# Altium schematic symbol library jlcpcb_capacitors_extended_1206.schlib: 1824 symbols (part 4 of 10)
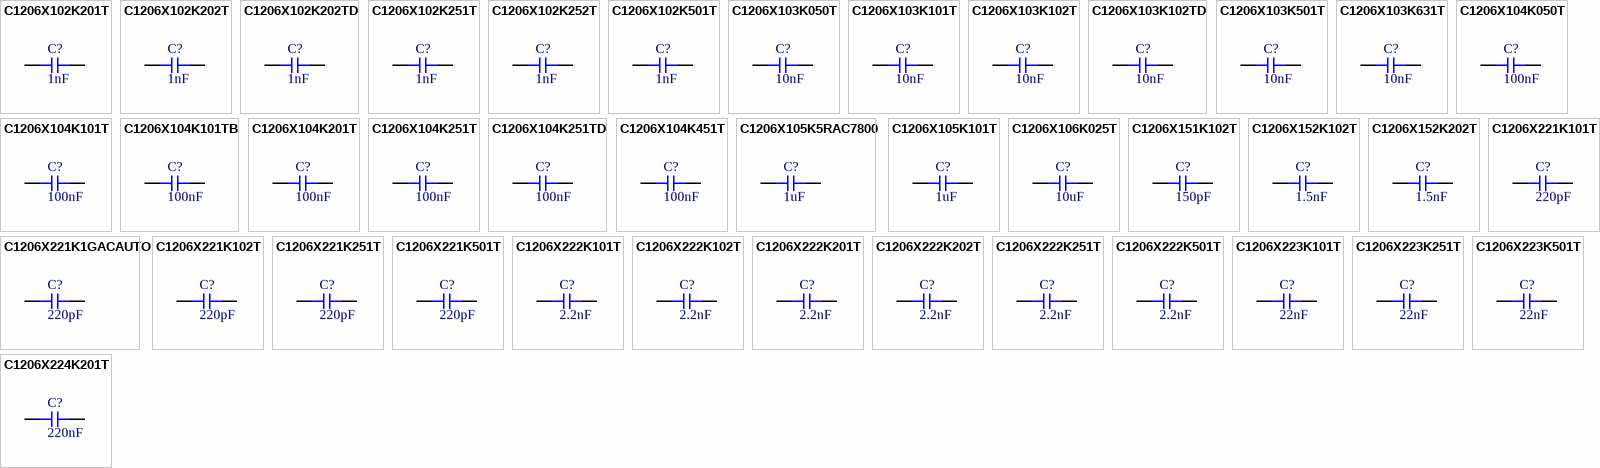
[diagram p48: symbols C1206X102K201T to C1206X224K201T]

## C1206X104K451T
designator C?  Capacitance: 100nF  (hidden comment: *)
Capacitor, Ceramic (MLCC), 100nF, ±10%, 450V, X7R, ±10%, SMD 1206; Manufacturer: IHHEC(HOLY STONE ENTERPRISE CO., LTD); Manufacturer Part Number: C1206X104K451T
footprint CAP-1206 (1206 (3216M) Capacitor)
pins: 1, 2

## C1206X105K5RAC7800
designator C?  Capacitance: 1uF  (hidden comment: *)
Capacitor, Ceramic (MLCC), 1uF, ±10%, 50V, X7R, ±10%, SMD 1206; Manufacturer: KEMET; Manufacturer Part Number: C1206X105K5RAC7800
footprint CAP-1206 (1206 (3216M) Capacitor)
pins: 1, 2

## C1206X105K101T
designator C?  Capacitance: 1uF  (hidden comment: *)
Capacitor, Ceramic (MLCC), 1uF, ±10%, 100V, X7R, ±10%, SMD 1206; Manufacturer: IHHEC(HOLY STONE ENTERPRISE CO., LTD); Manufacturer Part Number: C1206X105K101T
footprint CAP-1206 (1206 (3216M) Capacitor)
pins: 1, 2

## C1206X106K025T
designator C?  Capacitance: 10uF  (hidden comment: *)
Capacitor, Ceramic (MLCC), 10uF, ±10%, 25V, X7R, ±10%, SMD 1206; Manufacturer: IHHEC(HOLY STONE ENTERPRISE CO., LTD); Manufacturer Part Number: C1206X106K025T
footprint CAP-1206 (1206 (3216M) Capacitor)
pins: 1, 2

## C1206X151K102T
designator C?  Capacitance: 150pF  (hidden comment: *)
Capacitor, Ceramic (MLCC), 150pF, ±10%, 1kV, X7R, ±10%, SMD 1206; Manufacturer: IHHEC(HOLY STONE ENTERPRISE CO., LTD); Manufacturer Part Number: C1206X151K102T
footprint CAP-1206 (1206 (3216M) Capacitor)
pins: 1, 2

## C1206X152K102T
designator C?  Capacitance: 1.5nF  (hidden comment: *)
Capacitor, Ceramic (MLCC), 1.5nF, ±10%, 1kV, X7R, ±10%, SMD 1206; Manufacturer: IHHEC(HOLY STONE ENTERPRISE CO., LTD); Manufacturer Part Number: C1206X152K102T
footprint CAP-1206 (1206 (3216M) Capacitor)
pins: 1, 2

## C1206X152K202T
designator C?  Capacitance: 1.5nF  (hidden comment: *)
Capacitor, Ceramic (MLCC), 1.5nF, ±10%, 2kV, X7R, ±10%, SMD 1206; Manufacturer: IHHEC(HOLY STONE ENTERPRISE CO., LTD); Manufacturer Part Number: C1206X152K202T
footprint CAP-1206 (1206 (3216M) Capacitor)
pins: 1, 2

## C1206X221K1GACAUTO
designator C?  Capacitance: 220pF  (hidden comment: *)
Capacitor, Ceramic (MLCC), 220pF, ±10%, 100V, C0G, ±10%, SMD 1206; Manufacturer: KEMET; Manufacturer Part Number: C1206X221K1GACAUTO
footprint CAP-1206 (1206 (3216M) Capacitor)
pins: 1, 2

## C1206X221K101T
designator C?  Capacitance: 220pF  (hidden comment: *)
Capacitor, Ceramic (MLCC), 220pF, ±10%, 100V, X7R, ±10%, SMD 1206; Manufacturer: IHHEC(HOLY STONE ENTERPRISE CO., LTD); Manufacturer Part Number: C1206X221K101T
footprint CAP-1206 (1206 (3216M) Capacitor)
pins: 1, 2

## C1206X221K102T
designator C?  Capacitance: 220pF  (hidden comment: *)
Capacitor, Ceramic (MLCC), 220pF, ±10%, 1kV, X7R, ±10%, SMD 1206; Manufacturer: IHHEC(HOLY STONE ENTERPRISE CO., LTD); Manufacturer Part Number: C1206X221K102T
footprint CAP-1206 (1206 (3216M) Capacitor)
pins: 1, 2

## C1206X221K251T
designator C?  Capacitance: 220pF  (hidden comment: *)
Capacitor, Ceramic (MLCC), 220pF, ±10%, 250V, X7R, ±10%, SMD 1206; Manufacturer: IHHEC(HOLY STONE ENTERPRISE CO., LTD); Manufacturer Part Number: C1206X221K251T
footprint CAP-1206 (1206 (3216M) Capacitor)
pins: 1, 2

## C1206X221K501T
designator C?  Capacitance: 220pF  (hidden comment: *)
Capacitor, Ceramic (MLCC), 220pF, ±10%, 500V, X7R, ±10%, SMD 1206; Manufacturer: IHHEC(HOLY STONE ENTERPRISE CO., LTD); Manufacturer Part Number: C1206X221K501T
footprint CAP-1206 (1206 (3216M) Capacitor)
pins: 1, 2

## C1206X222K101T
designator C?  Capacitance: 2.2nF  (hidden comment: *)
Capacitor, Ceramic (MLCC), 2.2nF, ±10%, 100V, X7R, ±10%, SMD 1206; Manufacturer: IHHEC(HOLY STONE ENTERPRISE CO., LTD); Manufacturer Part Number: C1206X222K101T
footprint CAP-1206 (1206 (3216M) Capacitor)
pins: 1, 2

## C1206X222K102T
designator C?  Capacitance: 2.2nF  (hidden comment: *)
Capacitor, Ceramic (MLCC), 2.2nF, ±10%, 1kV, X7R, ±10%, SMD 1206; Manufacturer: IHHEC(HOLY STONE ENTERPRISE CO., LTD); Manufacturer Part Number: C1206X222K102T
footprint CAP-1206 (1206 (3216M) Capacitor)
pins: 1, 2

## C1206X222K201T
designator C?  Capacitance: 2.2nF  (hidden comment: *)
Capacitor, Ceramic (MLCC), 2.2nF, ±10%, 200V, X7R, ±10%, SMD 1206; Manufacturer: IHHEC(HOLY STONE ENTERPRISE CO., LTD); Manufacturer Part Number: C1206X222K201T
footprint CAP-1206 (1206 (3216M) Capacitor)
pins: 1, 2

## C1206X222K202T
designator C?  Capacitance: 2.2nF  (hidden comment: *)
Capacitor, Ceramic (MLCC), 2.2nF, ±10%, 2kV, X7R, ±10%, SMD 1206; Manufacturer: IHHEC(HOLY STONE ENTERPRISE CO., LTD); Manufacturer Part Number: C1206X222K202T
footprint CAP-1206 (1206 (3216M) Capacitor)
pins: 1, 2

## C1206X222K251T
designator C?  Capacitance: 2.2nF  (hidden comment: *)
Capacitor, Ceramic (MLCC), 2.2nF, ±10%, 250V, X7R, ±10%, SMD 1206; Manufacturer: IHHEC(HOLY STONE ENTERPRISE CO., LTD); Manufacturer Part Number: C1206X222K251T
footprint CAP-1206 (1206 (3216M) Capacitor)
pins: 1, 2

## C1206X222K501T
designator C?  Capacitance: 2.2nF  (hidden comment: *)
Capacitor, Ceramic (MLCC), 2.2nF, ±10%, 500V, X7R, ±10%, SMD 1206; Manufacturer: IHHEC(HOLY STONE ENTERPRISE CO., LTD); Manufacturer Part Number: C1206X222K501T
footprint CAP-1206 (1206 (3216M) Capacitor)
pins: 1, 2

## C1206X223K101T
designator C?  Capacitance: 22nF  (hidden comment: *)
Capacitor, Ceramic (MLCC), 22nF, ±10%, 100V, X7R, ±10%, SMD 1206; Manufacturer: IHHEC(HOLY STONE ENTERPRISE CO., LTD); Manufacturer Part Number: C1206X223K101T
footprint CAP-1206 (1206 (3216M) Capacitor)
pins: 1, 2

## C1206X223K251T
designator C?  Capacitance: 22nF  (hidden comment: *)
Capacitor, Ceramic (MLCC), 22nF, ±10%, 250V, X7R, ±10%, SMD 1206; Manufacturer: IHHEC(HOLY STONE ENTERPRISE CO., LTD); Manufacturer Part Number: C1206X223K251T
footprint CAP-1206 (1206 (3216M) Capacitor)
pins: 1, 2

## C1206X223K501T
designator C?  Capacitance: 22nF  (hidden comment: *)
Capacitor, Ceramic (MLCC), 22nF, ±10%, 500V, X7R, ±10%, SMD 1206; Manufacturer: IHHEC(HOLY STONE ENTERPRISE CO., LTD); Manufacturer Part Number: C1206X223K501T
footprint CAP-1206 (1206 (3216M) Capacitor)
pins: 1, 2

## C1206X224K201T
designator C?  Capacitance: 220nF  (hidden comment: *)
Capacitor, Ceramic (MLCC), 220nF, ±10%, 200V, X7R, ±10%, SMD 1206; Manufacturer: IHHEC(HOLY STONE ENTERPRISE CO., LTD); Manufacturer Part Number: C1206X224K201T
footprint CAP-1206 (1206 (3216M) Capacitor)
pins: 1, 2

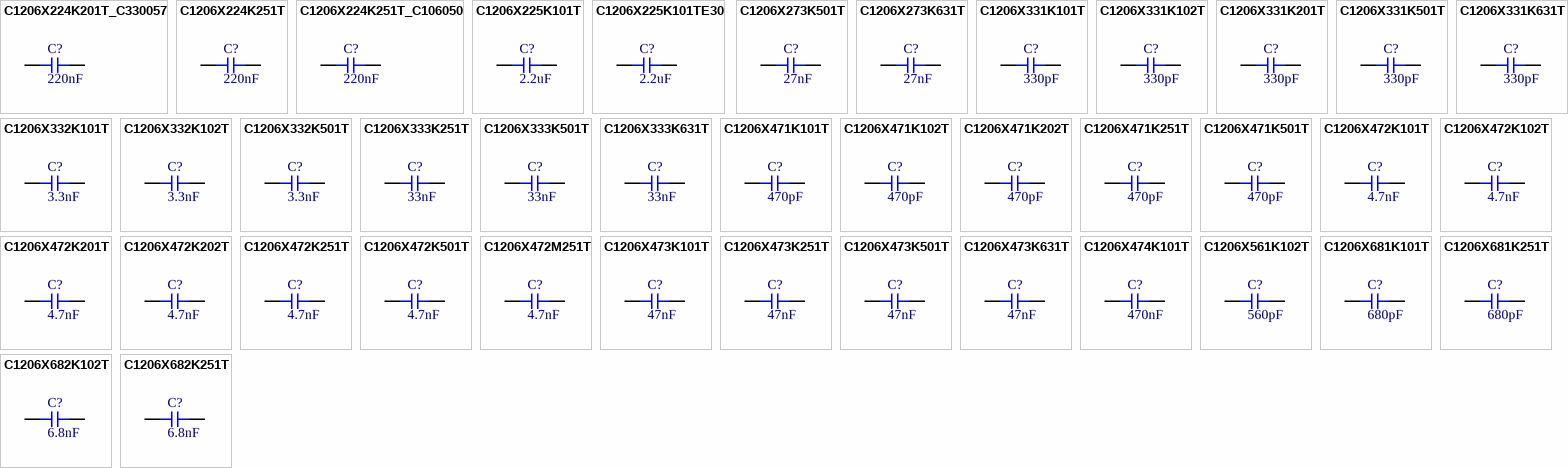
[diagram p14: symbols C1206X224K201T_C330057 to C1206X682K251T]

## C1206X224K201T_C330057
designator C?  Capacitance: 220nF  (hidden comment: *)
Capacitor, Ceramic (MLCC), 220nF, ±10%, 200V, X7R, ±10%, SMD 1206; Manufacturer: IHHEC(HOLY STONE ENTERPRISE CO., LTD); Manufacturer Part Number: C1206X224K201T
footprint CAP-1206 (1206 (3216M) Capacitor)
pins: 1, 2

## C1206X224K251T
designator C?  Capacitance: 220nF  (hidden comment: *)
Capacitor, Ceramic (MLCC), 220nF, ±10%, 250V, X7R, ±10%, SMD 1206; Manufacturer: IHHEC(HOLY STONE ENTERPRISE CO., LTD); Manufacturer Part Number: C1206X224K251T
footprint CAP-1206 (1206 (3216M) Capacitor)
pins: 1, 2

## C1206X224K251T_C106050
designator C?  Capacitance: 220nF  (hidden comment: *)
Capacitor, Ceramic (MLCC), 220nF, ±10%, 250V, X7R, ±10%, SMD 1206; Manufacturer: IHHEC(HOLY STONE ENTERPRISE CO., LTD); Manufacturer Part Number: C1206X224K251T
footprint CAP-1206 (1206 (3216M) Capacitor)
pins: 1, 2

## C1206X225K101T
designator C?  Capacitance: 2.2uF  (hidden comment: *)
Capacitor, Ceramic (MLCC), 2.2uF, ±10%, 100V, X7R, ±10%, SMD 1206; Manufacturer: IHHEC(HOLY STONE ENTERPRISE CO., LTD); Manufacturer Part Number: C1206X225K101T
footprint CAP-1206 (1206 (3216M) Capacitor)
pins: 1, 2

## C1206X225K101TE30
designator C?  Capacitance: 2.2uF  (hidden comment: *)
Capacitor, Ceramic (MLCC), 2.2uF, ±10%, 100V, X7R, ±10%, SMD 1206; Manufacturer: IHHEC(HOLY STONE ENTERPRISE CO., LTD); Manufacturer Part Number: C1206X225K101TE30
footprint CAP-1206 (1206 (3216M) Capacitor)
pins: 1, 2

## C1206X273K501T
designator C?  Capacitance: 27nF  (hidden comment: *)
Capacitor, Ceramic (MLCC), 27nF, ±10%, 500V, X7R, ±10%, SMD 1206; Manufacturer: IHHEC(HOLY STONE ENTERPRISE CO., LTD); Manufacturer Part Number: C1206X273K501T
footprint CAP-1206 (1206 (3216M) Capacitor)
pins: 1, 2

## C1206X273K631T
designator C?  Capacitance: 27nF  (hidden comment: *)
Capacitor, Ceramic (MLCC), 27nF, ±10%, 630V, X7R, ±10%, SMD 1206; Manufacturer: IHHEC(HOLY STONE ENTERPRISE CO., LTD); Manufacturer Part Number: C1206X273K631T
footprint CAP-1206 (1206 (3216M) Capacitor)
pins: 1, 2

## C1206X331K101T
designator C?  Capacitance: 330pF  (hidden comment: *)
Capacitor, Ceramic (MLCC), 330pF, ±10%, 100V, X7R, ±10%, SMD 1206; Manufacturer: IHHEC(HOLY STONE ENTERPRISE CO., LTD); Manufacturer Part Number: C1206X331K101T
footprint CAP-1206 (1206 (3216M) Capacitor)
pins: 1, 2

## C1206X331K102T
designator C?  Capacitance: 330pF  (hidden comment: *)
Capacitor, Ceramic (MLCC), 330pF, ±10%, 1kV, X7R, ±10%, SMD 1206; Manufacturer: IHHEC(HOLY STONE ENTERPRISE CO., LTD); Manufacturer Part Number: C1206X331K102T
footprint CAP-1206 (1206 (3216M) Capacitor)
pins: 1, 2

## C1206X331K201T
designator C?  Capacitance: 330pF  (hidden comment: *)
Capacitor, Ceramic (MLCC), 330pF, ±10%, 200V, X7R, ±10%, SMD 1206; Manufacturer: IHHEC(HOLY STONE ENTERPRISE CO., LTD); Manufacturer Part Number: C1206X331K201T
footprint CAP-1206 (1206 (3216M) Capacitor)
pins: 1, 2

## C1206X331K501T
designator C?  Capacitance: 330pF  (hidden comment: *)
Capacitor, Ceramic (MLCC), 330pF, ±10%, 500V, X7R, ±10%, SMD 1206; Manufacturer: IHHEC(HOLY STONE ENTERPRISE CO., LTD); Manufacturer Part Number: C1206X331K501T
footprint CAP-1206 (1206 (3216M) Capacitor)
pins: 1, 2

## C1206X331K631T
designator C?  Capacitance: 330pF  (hidden comment: *)
Capacitor, Ceramic (MLCC), 330pF, ±10%, 630V, X7R, ±10%, SMD 1206; Manufacturer: IHHEC(HOLY STONE ENTERPRISE CO., LTD); Manufacturer Part Number: C1206X331K631T
footprint CAP-1206 (1206 (3216M) Capacitor)
pins: 1, 2

## C1206X332K101T
designator C?  Capacitance: 3.3nF  (hidden comment: *)
Capacitor, Ceramic (MLCC), 3.3nF, ±10%, 100V, X7R, ±10%, SMD 1206; Manufacturer: IHHEC(HOLY STONE ENTERPRISE CO., LTD); Manufacturer Part Number: C1206X332K101T
footprint CAP-1206 (1206 (3216M) Capacitor)
pins: 1, 2

## C1206X332K102T
designator C?  Capacitance: 3.3nF  (hidden comment: *)
Capacitor, Ceramic (MLCC), 3.3nF, ±10%, 1kV, X7R, ±10%, SMD 1206; Manufacturer: IHHEC(HOLY STONE ENTERPRISE CO., LTD); Manufacturer Part Number: C1206X332K102T
footprint CAP-1206 (1206 (3216M) Capacitor)
pins: 1, 2

## C1206X332K501T
designator C?  Capacitance: 3.3nF  (hidden comment: *)
Capacitor, Ceramic (MLCC), 3.3nF, ±10%, 500V, X7R, ±10%, SMD 1206; Manufacturer: IHHEC(HOLY STONE ENTERPRISE CO., LTD); Manufacturer Part Number: C1206X332K501T
footprint CAP-1206 (1206 (3216M) Capacitor)
pins: 1, 2

## C1206X333K251T
designator C?  Capacitance: 33nF  (hidden comment: *)
Capacitor, Ceramic (MLCC), 33nF, ±10%, 250V, X7R, ±10%, SMD 1206; Manufacturer: IHHEC(HOLY STONE ENTERPRISE CO., LTD); Manufacturer Part Number: C1206X333K251T
footprint CAP-1206 (1206 (3216M) Capacitor)
pins: 1, 2

## C1206X333K501T
designator C?  Capacitance: 33nF  (hidden comment: *)
Capacitor, Ceramic (MLCC), 33nF, ±10%, 500V, X7R, ±10%, SMD 1206; Manufacturer: IHHEC(HOLY STONE ENTERPRISE CO., LTD); Manufacturer Part Number: C1206X333K501T
footprint CAP-1206 (1206 (3216M) Capacitor)
pins: 1, 2

## C1206X333K631T
designator C?  Capacitance: 33nF  (hidden comment: *)
Capacitor, Ceramic (MLCC), 33nF, ±10%, 630V, X7R, ±10%, SMD 1206; Manufacturer: IHHEC(HOLY STONE ENTERPRISE CO., LTD); Manufacturer Part Number: C1206X333K631T
footprint CAP-1206 (1206 (3216M) Capacitor)
pins: 1, 2

## C1206X471K101T
designator C?  Capacitance: 470pF  (hidden comment: *)
Capacitor, Ceramic (MLCC), 470pF, ±10%, 100V, X7R, ±10%, SMD 1206; Manufacturer: IHHEC(HOLY STONE ENTERPRISE CO., LTD); Manufacturer Part Number: C1206X471K101T
footprint CAP-1206 (1206 (3216M) Capacitor)
pins: 1, 2

## C1206X471K102T
designator C?  Capacitance: 470pF  (hidden comment: *)
Capacitor, Ceramic (MLCC), 470pF, ±10%, 1kV, X7R, ±10%, SMD 1206; Manufacturer: IHHEC(HOLY STONE ENTERPRISE CO., LTD); Manufacturer Part Number: C1206X471K102T
footprint CAP-1206 (1206 (3216M) Capacitor)
pins: 1, 2

## C1206X471K202T
designator C?  Capacitance: 470pF  (hidden comment: *)
Capacitor, Ceramic (MLCC), 470pF, ±10%, 2kV, X7R, ±10%, SMD 1206; Manufacturer: IHHEC(HOLY STONE ENTERPRISE CO., LTD); Manufacturer Part Number: C1206X471K202T
footprint CAP-1206 (1206 (3216M) Capacitor)
pins: 1, 2

## C1206X471K251T
designator C?  Capacitance: 470pF  (hidden comment: *)
Capacitor, Ceramic (MLCC), 470pF, ±10%, 250V, X7R, ±10%, SMD 1206; Manufacturer: IHHEC(HOLY STONE ENTERPRISE CO., LTD); Manufacturer Part Number: C1206X471K251T
footprint CAP-1206 (1206 (3216M) Capacitor)
pins: 1, 2

## C1206X471K501T
designator C?  Capacitance: 470pF  (hidden comment: *)
Capacitor, Ceramic (MLCC), 470pF, ±10%, 500V, X7R, ±10%, SMD 1206; Manufacturer: IHHEC(HOLY STONE ENTERPRISE CO., LTD); Manufacturer Part Number: C1206X471K501T
footprint CAP-1206 (1206 (3216M) Capacitor)
pins: 1, 2

## C1206X472K101T
designator C?  Capacitance: 4.7nF  (hidden comment: *)
Capacitor, Ceramic (MLCC), 4.7nF, ±10%, 100V, X7R, ±10%, SMD 1206; Manufacturer: IHHEC(HOLY STONE ENTERPRISE CO., LTD); Manufacturer Part Number: C1206X472K101T
footprint CAP-1206 (1206 (3216M) Capacitor)
pins: 1, 2

## C1206X472K102T
designator C?  Capacitance: 4.7nF  (hidden comment: *)
Capacitor, Ceramic (MLCC), 4.7nF, ±10%, 1kV, X7R, ±10%, SMD 1206; Manufacturer: IHHEC(HOLY STONE ENTERPRISE CO., LTD); Manufacturer Part Number: C1206X472K102T
footprint CAP-1206 (1206 (3216M) Capacitor)
pins: 1, 2

## C1206X472K201T
designator C?  Capacitance: 4.7nF  (hidden comment: *)
Capacitor, Ceramic (MLCC), 4.7nF, ±10%, 200V, X7R, ±10%, SMD 1206; Manufacturer: IHHEC(HOLY STONE ENTERPRISE CO., LTD); Manufacturer Part Number: C1206X472K201T
footprint CAP-1206 (1206 (3216M) Capacitor)
pins: 1, 2

## C1206X472K202T
designator C?  Capacitance: 4.7nF  (hidden comment: *)
Capacitor, Ceramic (MLCC), 4.7nF, ±10%, 2kV, X7R, ±10%, SMD 1206; Manufacturer: IHHEC(HOLY STONE ENTERPRISE CO., LTD); Manufacturer Part Number: C1206X472K202T
footprint CAP-1206 (1206 (3216M) Capacitor)
pins: 1, 2

## C1206X472K251T
designator C?  Capacitance: 4.7nF  (hidden comment: *)
Capacitor, Ceramic (MLCC), 4.7nF, ±10%, 250V, X7R, ±10%, SMD 1206; Manufacturer: IHHEC(HOLY STONE ENTERPRISE CO., LTD); Manufacturer Part Number: C1206X472K251T
footprint CAP-1206 (1206 (3216M) Capacitor)
pins: 1, 2

## C1206X472K501T
designator C?  Capacitance: 4.7nF  (hidden comment: *)
Capacitor, Ceramic (MLCC), 4.7nF, ±10%, 500V, X7R, ±10%, SMD 1206; Manufacturer: IHHEC(HOLY STONE ENTERPRISE CO., LTD); Manufacturer Part Number: C1206X472K501T
footprint CAP-1206 (1206 (3216M) Capacitor)
pins: 1, 2

## C1206X472M251T
designator C?  Capacitance: 4.7nF  (hidden comment: *)
Capacitor, Ceramic (MLCC), 4.7nF, ±20%, 250V, X7R, ±20%, SMD 1206; Manufacturer: IHHEC(HOLY STONE ENTERPRISE CO., LTD); Manufacturer Part Number: C1206X472M251T
footprint CAP-1206 (1206 (3216M) Capacitor)
pins: 1, 2

## C1206X473K101T
designator C?  Capacitance: 47nF  (hidden comment: *)
Capacitor, Ceramic (MLCC), 47nF, ±10%, 100V, X7R, ±10%, SMD 1206; Manufacturer: IHHEC(HOLY STONE ENTERPRISE CO., LTD); Manufacturer Part Number: C1206X473K101T
footprint CAP-1206 (1206 (3216M) Capacitor)
pins: 1, 2

## C1206X473K251T
designator C?  Capacitance: 47nF  (hidden comment: *)
Capacitor, Ceramic (MLCC), 47nF, ±10%, 250V, X7R, ±10%, SMD 1206; Manufacturer: IHHEC(HOLY STONE ENTERPRISE CO., LTD); Manufacturer Part Number: C1206X473K251T
footprint CAP-1206 (1206 (3216M) Capacitor)
pins: 1, 2

## C1206X473K501T
designator C?  Capacitance: 47nF  (hidden comment: *)
Capacitor, Ceramic (MLCC), 47nF, ±10%, 500V, X7R, ±10%, SMD 1206; Manufacturer: IHHEC(HOLY STONE ENTERPRISE CO., LTD); Manufacturer Part Number: C1206X473K501T
footprint CAP-1206 (1206 (3216M) Capacitor)
pins: 1, 2

## C1206X473K631T
designator C?  Capacitance: 47nF  (hidden comment: *)
Capacitor, Ceramic (MLCC), 47nF, ±10%, 630V, X7R, ±10%, SMD 1206; Manufacturer: IHHEC(HOLY STONE ENTERPRISE CO., LTD); Manufacturer Part Number: C1206X473K631T
footprint CAP-1206 (1206 (3216M) Capacitor)
pins: 1, 2

## C1206X474K101T
designator C?  Capacitance: 470nF  (hidden comment: *)
Capacitor, Ceramic (MLCC), 470nF, ±10%, 100V, X7R, ±10%, SMD 1206; Manufacturer: IHHEC(HOLY STONE ENTERPRISE CO., LTD); Manufacturer Part Number: C1206X474K101T
footprint CAP-1206 (1206 (3216M) Capacitor)
pins: 1, 2

## C1206X561K102T
designator C?  Capacitance: 560pF  (hidden comment: *)
Capacitor, Ceramic (MLCC), 560pF, ±10%, 1kV, X7R, ±10%, SMD 1206; Manufacturer: IHHEC(HOLY STONE ENTERPRISE CO., LTD); Manufacturer Part Number: C1206X561K102T
footprint CAP-1206 (1206 (3216M) Capacitor)
pins: 1, 2

## C1206X681K101T
designator C?  Capacitance: 680pF  (hidden comment: *)
Capacitor, Ceramic (MLCC), 680pF, ±10%, 100V, X7R, ±10%, SMD 1206; Manufacturer: IHHEC(HOLY STONE ENTERPRISE CO., LTD); Manufacturer Part Number: C1206X681K101T
footprint CAP-1206 (1206 (3216M) Capacitor)
pins: 1, 2

## C1206X681K251T
designator C?  Capacitance: 680pF  (hidden comment: *)
Capacitor, Ceramic (MLCC), 680pF, ±10%, 250V, X7R, ±10%, SMD 1206; Manufacturer: IHHEC(HOLY STONE ENTERPRISE CO., LTD); Manufacturer Part Number: C1206X681K251T
footprint CAP-1206 (1206 (3216M) Capacitor)
pins: 1, 2

## C1206X682K102T
designator C?  Capacitance: 6.8nF  (hidden comment: *)
Capacitor, Ceramic (MLCC), 6.8nF, ±10%, 1kV, X7R, ±10%, SMD 1206; Manufacturer: IHHEC(HOLY STONE ENTERPRISE CO., LTD); Manufacturer Part Number: C1206X682K102T
footprint CAP-1206 (1206 (3216M) Capacitor)
pins: 1, 2

## C1206X682K251T
designator C?  Capacitance: 6.8nF  (hidden comment: *)
Capacitor, Ceramic (MLCC), 6.8nF, ±10%, 250V, X7R, ±10%, SMD 1206; Manufacturer: IHHEC(HOLY STONE ENTERPRISE CO., LTD); Manufacturer Part Number: C1206X682K251T
footprint CAP-1206 (1206 (3216M) Capacitor)
pins: 1, 2

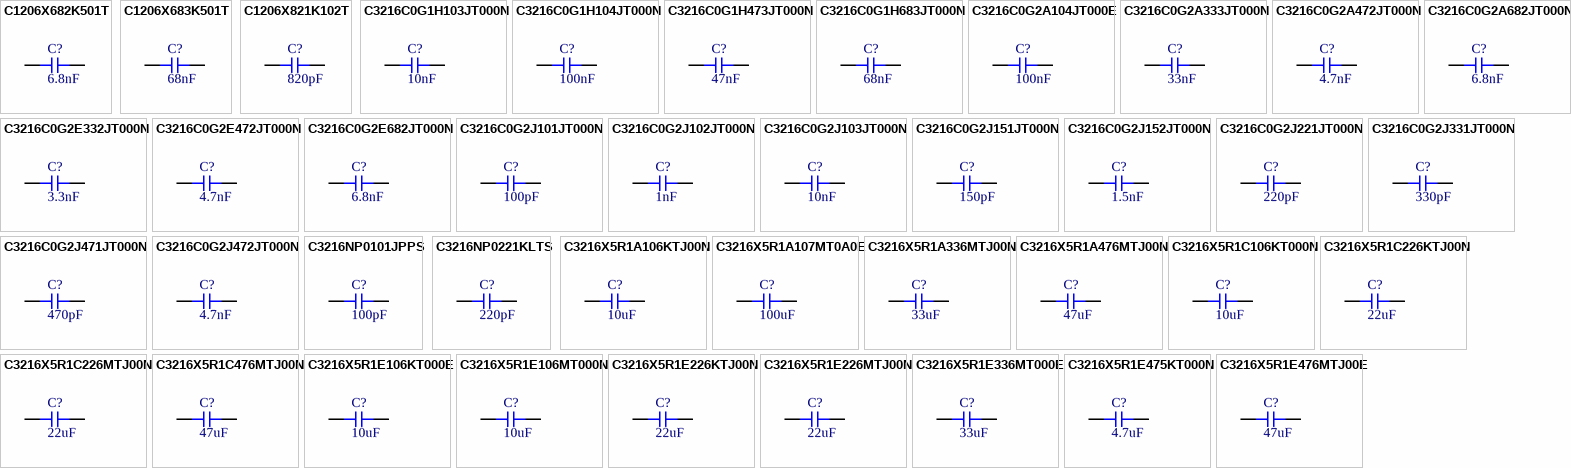
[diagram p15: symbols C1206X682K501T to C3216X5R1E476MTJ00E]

## C1206X682K501T
designator C?  Capacitance: 6.8nF  (hidden comment: *)
Capacitor, Ceramic (MLCC), 6.8nF, ±10%, 500V, X7R, ±10%, SMD 1206; Manufacturer: IHHEC(HOLY STONE ENTERPRISE CO., LTD); Manufacturer Part Number: C1206X682K501T
footprint CAP-1206 (1206 (3216M) Capacitor)
pins: 1, 2

## C1206X683K501T
designator C?  Capacitance: 68nF  (hidden comment: *)
Capacitor, Ceramic (MLCC), 68nF, ±10%, 500V, X7R, ±10%, SMD 1206; Manufacturer: IHHEC(HOLY STONE ENTERPRISE CO., LTD); Manufacturer Part Number: C1206X683K501T
footprint CAP-1206 (1206 (3216M) Capacitor)
pins: 1, 2

## C1206X821K102T
designator C?  Capacitance: 820pF  (hidden comment: *)
Capacitor, Ceramic (MLCC), 820pF, ±10%, 1kV, X7R, ±10%, SMD 1206; Manufacturer: IHHEC(HOLY STONE ENTERPRISE CO., LTD); Manufacturer Part Number: C1206X821K102T
footprint CAP-1206 (1206 (3216M) Capacitor)
pins: 1, 2

## C3216C0G1H103JT000N
designator C?  Capacitance: 10nF  (hidden comment: *)
Capacitor, Ceramic (MLCC), 10nF, ±5%, 50V, C0G, ±5%, SMD 1206; Manufacturer: TDK; Manufacturer Part Number: C3216C0G1H103JT000N
footprint CAP-1206 (1206 (3216M) Capacitor)
pins: 1, 2

## C3216C0G1H104JT000N
designator C?  Capacitance: 100nF  (hidden comment: *)
Capacitor, Ceramic (MLCC), 100nF, ±5%, 50V, C0G, ±5%, SMD 1206; Manufacturer: TDK; Manufacturer Part Number: C3216C0G1H104JT000N
footprint CAP-1206 (1206 (3216M) Capacitor)
pins: 1, 2

## C3216C0G1H473JT000N
designator C?  Capacitance: 47nF  (hidden comment: *)
Capacitor, Ceramic (MLCC), 47nF, ±5%, 50V, C0G, ±5%, SMD 1206; Manufacturer: TDK; Manufacturer Part Number: C3216C0G1H473JT000N
footprint CAP-1206 (1206 (3216M) Capacitor)
pins: 1, 2

## C3216C0G1H683JT000N
designator C?  Capacitance: 68nF  (hidden comment: *)
Capacitor, Ceramic (MLCC), 68nF, ±5%, 50V, C0G, ±5%, SMD 1206; Manufacturer: TDK; Manufacturer Part Number: C3216C0G1H683JT000N
footprint CAP-1206 (1206 (3216M) Capacitor)
pins: 1, 2

## C3216C0G2A104JT000E
designator C?  Capacitance: 100nF  (hidden comment: *)
Capacitor, Ceramic (MLCC), 100nF, ±5%, 100V, C0G, ±5%, SMD 1206; Manufacturer: TDK; Manufacturer Part Number: C3216C0G2A104JT000E
footprint CAP-1206 (1206 (3216M) Capacitor)
pins: 1, 2

## C3216C0G2A333JT000N
designator C?  Capacitance: 33nF  (hidden comment: *)
Capacitor, Ceramic (MLCC), 33nF, ±5%, 100V, C0G, ±5%, SMD 1206; Manufacturer: TDK; Manufacturer Part Number: C3216C0G2A333JT000N
footprint CAP-1206 (1206 (3216M) Capacitor)
pins: 1, 2

## C3216C0G2A472JT000N
designator C?  Capacitance: 4.7nF  (hidden comment: *)
Capacitor, Ceramic (MLCC), 4.7nF, ±5%, 100V, C0G, ±5%, SMD 1206; Manufacturer: TDK; Manufacturer Part Number: C3216C0G2A472JT000N
footprint CAP-1206 (1206 (3216M) Capacitor)
pins: 1, 2

## C3216C0G2A682JT000N
designator C?  Capacitance: 6.8nF  (hidden comment: *)
Capacitor, Ceramic (MLCC), 6.8nF, ±5%, 100V, C0G, ±5%, SMD 1206; Manufacturer: TDK; Manufacturer Part Number: C3216C0G2A682JT000N
footprint CAP-1206 (1206 (3216M) Capacitor)
pins: 1, 2

## C3216C0G2E332JT000N
designator C?  Capacitance: 3.3nF  (hidden comment: *)
Capacitor, Ceramic (MLCC), 3.3nF, ±5%, 250V, C0G, ±5%, SMD 1206; Manufacturer: TDK; Manufacturer Part Number: C3216C0G2E332JT000N
footprint CAP-1206 (1206 (3216M) Capacitor)
pins: 1, 2

## C3216C0G2E472JT000N
designator C?  Capacitance: 4.7nF  (hidden comment: *)
Capacitor, Ceramic (MLCC), 4.7nF, ±5%, 250V, C0G, ±5%, SMD 1206; Manufacturer: TDK; Manufacturer Part Number: C3216C0G2E472JT000N
footprint CAP-1206 (1206 (3216M) Capacitor)
pins: 1, 2

## C3216C0G2E682JT000N
designator C?  Capacitance: 6.8nF  (hidden comment: *)
Capacitor, Ceramic (MLCC), 6.8nF, ±5%, 250V, C0G, ±5%, SMD 1206; Manufacturer: TDK; Manufacturer Part Number: C3216C0G2E682JT000N
footprint CAP-1206 (1206 (3216M) Capacitor)
pins: 1, 2

## C3216C0G2J101JT000N
designator C?  Capacitance: 100pF  (hidden comment: *)
Capacitor, Ceramic (MLCC), 100pF, ±5%, 630V, C0G, ±5%, SMD 1206; Manufacturer: TDK; Manufacturer Part Number: C3216C0G2J101JT000N
footprint CAP-1206 (1206 (3216M) Capacitor)
pins: 1, 2

## C3216C0G2J102JT000N
designator C?  Capacitance: 1nF  (hidden comment: *)
Capacitor, Ceramic (MLCC), 1nF, ±5%, 630V, C0G, ±5%, SMD 1206; Manufacturer: TDK; Manufacturer Part Number: C3216C0G2J102JT000N
footprint CAP-1206 (1206 (3216M) Capacitor)
pins: 1, 2

## C3216C0G2J103JT000N
designator C?  Capacitance: 10nF  (hidden comment: *)
Capacitor, Ceramic (MLCC), 10nF, ±5%, 630V, C0G, ±5%, SMD 1206; Manufacturer: TDK; Manufacturer Part Number: C3216C0G2J103JT000N
footprint CAP-1206 (1206 (3216M) Capacitor)
pins: 1, 2

## C3216C0G2J151JT000N
designator C?  Capacitance: 150pF  (hidden comment: *)
Capacitor, Ceramic (MLCC), 150pF, ±5%, 630V, C0G, ±5%, SMD 1206; Manufacturer: TDK; Manufacturer Part Number: C3216C0G2J151JT000N
footprint CAP-1206 (1206 (3216M) Capacitor)
pins: 1, 2

## C3216C0G2J152JT000N
designator C?  Capacitance: 1.5nF  (hidden comment: *)
Capacitor, Ceramic (MLCC), 1.5nF, ±5%, 630V, C0G, ±5%, SMD 1206; Manufacturer: TDK; Manufacturer Part Number: C3216C0G2J152JT000N
footprint CAP-1206 (1206 (3216M) Capacitor)
pins: 1, 2

## C3216C0G2J221JT000N
designator C?  Capacitance: 220pF  (hidden comment: *)
Capacitor, Ceramic (MLCC), 220pF, ±5%, 630V, C0G, ±5%, SMD 1206; Manufacturer: TDK; Manufacturer Part Number: C3216C0G2J221JT000N
footprint CAP-1206 (1206 (3216M) Capacitor)
pins: 1, 2

## C3216C0G2J331JT000N
designator C?  Capacitance: 330pF  (hidden comment: *)
Capacitor, Ceramic (MLCC), 330pF, ±5%, 630V, C0G, ±5%, SMD 1206; Manufacturer: TDK; Manufacturer Part Number: C3216C0G2J331JT000N
footprint CAP-1206 (1206 (3216M) Capacitor)
pins: 1, 2

## C3216C0G2J471JT000N
designator C?  Capacitance: 470pF  (hidden comment: *)
Capacitor, Ceramic (MLCC), 470pF, ±5%, 630V, C0G, ±5%, SMD 1206; Manufacturer: TDK; Manufacturer Part Number: C3216C0G2J471JT000N
footprint CAP-1206 (1206 (3216M) Capacitor)
pins: 1, 2

## C3216C0G2J472JT000N
designator C?  Capacitance: 4.7nF  (hidden comment: *)
Capacitor, Ceramic (MLCC), 4.7nF, ±5%, 630V, C0G, ±5%, SMD 1206; Manufacturer: TDK; Manufacturer Part Number: C3216C0G2J472JT000N
footprint CAP-1206 (1206 (3216M) Capacitor)
pins: 1, 2

## C3216NP0101JPPS
designator C?  Capacitance: 100pF  (hidden comment: *)
Capacitor, Ceramic (MLCC), 100pF, ±5%, 1kV, NP0, ±5%, SMD 1206; Manufacturer: Darfon Elec; Manufacturer Part Number: C3216NP0101JPPS
footprint CAP-1206 (1206 (3216M) Capacitor)
pins: 1, 2

## C3216NP0221KLTS
designator C?  Capacitance: 220pF  (hidden comment: *)
Capacitor, Ceramic (MLCC), 220pF, ±10%, 500V, NP0, ±10%, SMD 1206; Manufacturer: Darfon Elec; Manufacturer Part Number: C3216NP0221KLTS
footprint CAP-1206 (1206 (3216M) Capacitor)
pins: 1, 2

## C3216X5R1A106KTJ00N
designator C?  Capacitance: 10uF  (hidden comment: *)
Capacitor, Ceramic (MLCC), 10uF, ±10%, 10V, X5R, ±10%, SMD 1206; Manufacturer: TDK; Manufacturer Part Number: C3216X5R1A106KTJ00N
footprint CAP-1206 (1206 (3216M) Capacitor)
pins: 1, 2

## C3216X5R1A107MT0A0E
designator C?  Capacitance: 100uF  (hidden comment: *)
Capacitor, Ceramic (MLCC), 100uF, ±20%, 10V, X5R, ±20%, SMD 1206; Manufacturer: TDK; Manufacturer Part Number: C3216X5R1A107MT0A0E
footprint CAP-1206 (1206 (3216M) Capacitor)
pins: 1, 2

## C3216X5R1A336MTJ00N
designator C?  Capacitance: 33uF  (hidden comment: *)
Capacitor, Ceramic (MLCC), 33uF, ±20%, 10V, X5R, ±20%, SMD 1206; Manufacturer: TDK; Manufacturer Part Number: C3216X5R1A336MTJ00N
footprint CAP-1206 (1206 (3216M) Capacitor)
pins: 1, 2

## C3216X5R1A476MTJ00N
designator C?  Capacitance: 47uF  (hidden comment: *)
Capacitor, Ceramic (MLCC), 47uF, ±20%, 10V, X5R, ±20%, SMD 1206; Manufacturer: TDK; Manufacturer Part Number: C3216X5R1A476MTJ00N
footprint CAP-1206 (1206 (3216M) Capacitor)
pins: 1, 2

## C3216X5R1C106KT000N
designator C?  Capacitance: 10uF  (hidden comment: *)
Capacitor, Ceramic (MLCC), 10uF, ±10%, 16V, X5R, ±10%, SMD 1206; Manufacturer: TDK; Manufacturer Part Number: C3216X5R1C106KT000N
footprint CAP-1206 (1206 (3216M) Capacitor)
pins: 1, 2

## C3216X5R1C226KTJ00N
designator C?  Capacitance: 22uF  (hidden comment: *)
Capacitor, Ceramic (MLCC), 22uF, ±10%, 16V, X5R, ±10%, SMD 1206; Manufacturer: TDK; Manufacturer Part Number: C3216X5R1C226KTJ00N
footprint CAP-1206 (1206 (3216M) Capacitor)
pins: 1, 2

## C3216X5R1C226MTJ00N
designator C?  Capacitance: 22uF  (hidden comment: *)
Capacitor, Ceramic (MLCC), 22uF, ±20%, 16V, X5R, ±20%, SMD 1206; Manufacturer: TDK; Manufacturer Part Number: C3216X5R1C226MTJ00N
footprint CAP-1206 (1206 (3216M) Capacitor)
pins: 1, 2

## C3216X5R1C476MTJ00N
designator C?  Capacitance: 47uF  (hidden comment: *)
Capacitor, Ceramic (MLCC), 47uF, ±20%, 16V, X5R, ±20%, SMD 1206; Manufacturer: TDK; Manufacturer Part Number: C3216X5R1C476MTJ00N
footprint CAP-1206 (1206 (3216M) Capacitor)
pins: 1, 2

## C3216X5R1E106KT000E
designator C?  Capacitance: 10uF  (hidden comment: *)
Capacitor, Ceramic (MLCC), 10uF, ±10%, 25V, X5R, ±10%, SMD 1206; Manufacturer: TDK; Manufacturer Part Number: C3216X5R1E106KT000E
footprint CAP-1206 (1206 (3216M) Capacitor)
pins: 1, 2

## C3216X5R1E106MT000N
designator C?  Capacitance: 10uF  (hidden comment: *)
Capacitor, Ceramic (MLCC), 10uF, ±20%, 25V, X5R, ±20%, SMD 1206; Manufacturer: TDK; Manufacturer Part Number: C3216X5R1E106MT000N
footprint CAP-1206 (1206 (3216M) Capacitor)
pins: 1, 2

## C3216X5R1E226KTJ00N
designator C?  Capacitance: 22uF  (hidden comment: *)
Capacitor, Ceramic (MLCC), 22uF, ±10%, 25V, X5R, ±10%, SMD 1206; Manufacturer: TDK; Manufacturer Part Number: C3216X5R1E226KTJ00N
footprint CAP-1206 (1206 (3216M) Capacitor)
pins: 1, 2

## C3216X5R1E226MTJ00N
designator C?  Capacitance: 22uF  (hidden comment: *)
Capacitor, Ceramic (MLCC), 22uF, ±20%, 25V, X5R, ±20%, SMD 1206; Manufacturer: TDK; Manufacturer Part Number: C3216X5R1E226MTJ00N
footprint CAP-1206 (1206 (3216M) Capacitor)
pins: 1, 2

## C3216X5R1E336MT000E
designator C?  Capacitance: 33uF  (hidden comment: *)
Capacitor, Ceramic (MLCC), 33uF, ±20%, 25V, X5R, ±20%, SMD 1206; Manufacturer: TDK; Manufacturer Part Number: C3216X5R1E336MT000E
footprint CAP-1206 (1206 (3216M) Capacitor)
pins: 1, 2

## C3216X5R1E475KT000N
designator C?  Capacitance: 4.7uF  (hidden comment: *)
Capacitor, Ceramic (MLCC), 4.7uF, ±10%, 25V, X5R, ±10%, SMD 1206; Manufacturer: TDK; Manufacturer Part Number: C3216X5R1E475KT000N
footprint CAP-1206 (1206 (3216M) Capacitor)
pins: 1, 2

## C3216X5R1E476MTJ00E
designator C?  Capacitance: 47uF  (hidden comment: *)
Capacitor, Ceramic (MLCC), 47uF, ±20%, 25V, X5R, ±20%, SMD 1206; Manufacturer: TDK; Manufacturer Part Number: C3216X5R1E476MTJ00E
footprint CAP-1206 (1206 (3216M) Capacitor)
pins: 1, 2

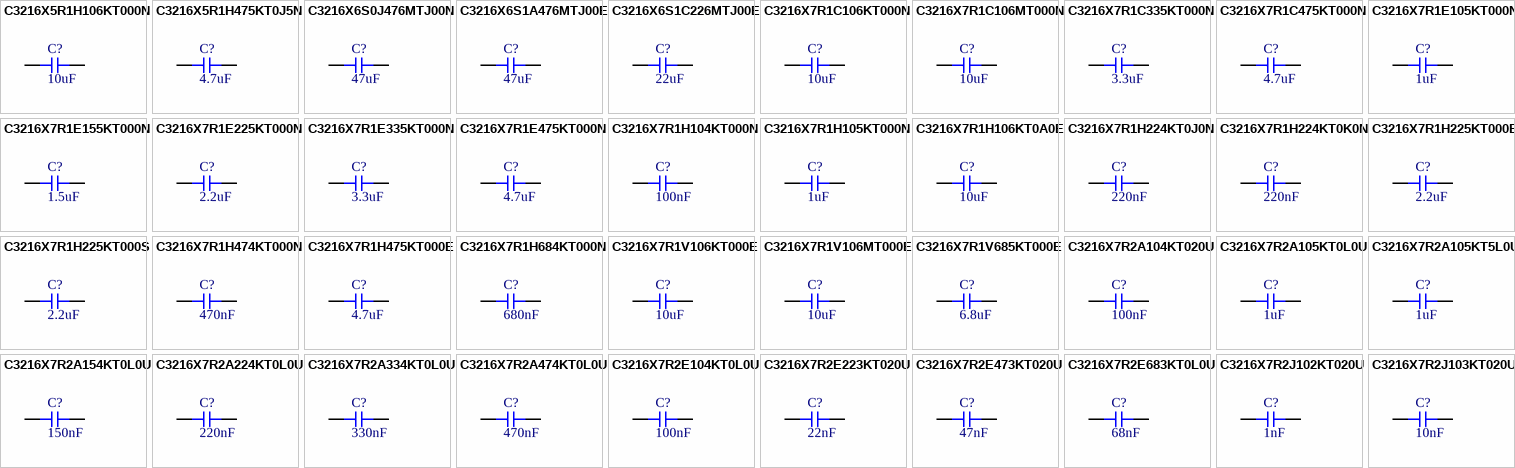
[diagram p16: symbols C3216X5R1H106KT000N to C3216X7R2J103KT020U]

## C3216X5R1H106KT000N
designator C?  Capacitance: 10uF  (hidden comment: *)
Capacitor, Ceramic (MLCC), 10uF, ±10%, 50V, X5R, ±10%, SMD 1206; Manufacturer: TDK; Manufacturer Part Number: C3216X5R1H106KT000N
footprint CAP-1206 (1206 (3216M) Capacitor)
pins: 1, 2

## C3216X5R1H475KT0J5N
designator C?  Capacitance: 4.7uF  (hidden comment: *)
Capacitor, Ceramic (MLCC), 4.7uF, ±10%, 50V, X5R, ±10%, SMD 1206; Manufacturer: TDK; Manufacturer Part Number: C3216X5R1H475KT0J5N
footprint CAP-1206 (1206 (3216M) Capacitor)
pins: 1, 2

## C3216X6S0J476MTJ00N
designator C?  Capacitance: 47uF  (hidden comment: *)
Capacitor, Ceramic (MLCC), 47uF, ±20%, 6.3V, X6S, ±20%, SMD 1206; Manufacturer: TDK; Manufacturer Part Number: C3216X6S0J476MTJ00N
footprint CAP-1206 (1206 (3216M) Capacitor)
pins: 1, 2

## C3216X6S1A476MTJ00E
designator C?  Capacitance: 47uF  (hidden comment: *)
Capacitor, Ceramic (MLCC), 47uF, ±20%, 10V, X6S, ±20%, SMD 1206; Manufacturer: TDK; Manufacturer Part Number: C3216X6S1A476MTJ00E
footprint CAP-1206 (1206 (3216M) Capacitor)
pins: 1, 2

## C3216X6S1C226MTJ00E
designator C?  Capacitance: 22uF  (hidden comment: *)
Capacitor, Ceramic (MLCC), 22uF, ±20%, 16V, X6S, ±20%, SMD 1206; Manufacturer: TDK; Manufacturer Part Number: C3216X6S1C226MTJ00E
footprint CAP-1206 (1206 (3216M) Capacitor)
pins: 1, 2

## C3216X7R1C106KT000N
designator C?  Capacitance: 10uF  (hidden comment: *)
Capacitor, Ceramic (MLCC), 10uF, ±10%, 16V, X7R, ±10%, SMD 1206; Manufacturer: TDK; Manufacturer Part Number: C3216X7R1C106KT000N
footprint CAP-1206 (1206 (3216M) Capacitor)
pins: 1, 2

## C3216X7R1C106MT000N
designator C?  Capacitance: 10uF  (hidden comment: *)
Capacitor, Ceramic (MLCC), 10uF, ±20%, 16V, X7R, ±20%, SMD 1206; Manufacturer: TDK; Manufacturer Part Number: C3216X7R1C106MT000N
footprint CAP-1206 (1206 (3216M) Capacitor)
pins: 1, 2

## C3216X7R1C335KT000N
designator C?  Capacitance: 3.3uF  (hidden comment: *)
Capacitor, Ceramic (MLCC), 3.3uF, ±10%, 16V, X7R, ±10%, SMD 1206; Manufacturer: TDK; Manufacturer Part Number: C3216X7R1C335KT000N
footprint CAP-1206 (1206 (3216M) Capacitor)
pins: 1, 2

## C3216X7R1C475KT000N
designator C?  Capacitance: 4.7uF  (hidden comment: *)
Capacitor, Ceramic (MLCC), 4.7uF, ±10%, 16V, X7R, ±10%, SMD 1206; Manufacturer: TDK; Manufacturer Part Number: C3216X7R1C475KT000N
footprint CAP-1206 (1206 (3216M) Capacitor)
pins: 1, 2

## C3216X7R1E105KT000N
designator C?  Capacitance: 1uF  (hidden comment: *)
Capacitor, Ceramic (MLCC), 1uF, ±10%, 25V, X7R, ±10%, SMD 1206; Manufacturer: TDK; Manufacturer Part Number: C3216X7R1E105KT000N
footprint CAP-1206 (1206 (3216M) Capacitor)
pins: 1, 2

## C3216X7R1E155KT000N
designator C?  Capacitance: 1.5uF  (hidden comment: *)
Capacitor, Ceramic (MLCC), 1.5uF, ±10%, 25V, X7R, ±10%, SMD 1206; Manufacturer: TDK; Manufacturer Part Number: C3216X7R1E155KT000N
footprint CAP-1206 (1206 (3216M) Capacitor)
pins: 1, 2

## C3216X7R1E225KT000N
designator C?  Capacitance: 2.2uF  (hidden comment: *)
Capacitor, Ceramic (MLCC), 2.2uF, ±10%, 25V, X7R, ±10%, SMD 1206; Manufacturer: TDK; Manufacturer Part Number: C3216X7R1E225KT000N
footprint CAP-1206 (1206 (3216M) Capacitor)
pins: 1, 2

## C3216X7R1E335KT000N
designator C?  Capacitance: 3.3uF  (hidden comment: *)
Capacitor, Ceramic (MLCC), 3.3uF, ±10%, 25V, X7R, ±10%, SMD 1206; Manufacturer: TDK; Manufacturer Part Number: C3216X7R1E335KT000N
footprint CAP-1206 (1206 (3216M) Capacitor)
pins: 1, 2

## C3216X7R1E475KT000N
designator C?  Capacitance: 4.7uF  (hidden comment: *)
Capacitor, Ceramic (MLCC), 4.7uF, ±10%, 25V, X7R, ±10%, SMD 1206; Manufacturer: TDK; Manufacturer Part Number: C3216X7R1E475KT000N
footprint CAP-1206 (1206 (3216M) Capacitor)
pins: 1, 2

## C3216X7R1H104KT000N
designator C?  Capacitance: 100nF  (hidden comment: *)
Capacitor, Ceramic (MLCC), 100nF, ±10%, 50V, X7R, ±10%, SMD 1206; Manufacturer: TDK; Manufacturer Part Number: C3216X7R1H104KT000N
footprint CAP-1206 (1206 (3216M) Capacitor)
pins: 1, 2

## C3216X7R1H105KT000N
designator C?  Capacitance: 1uF  (hidden comment: *)
Capacitor, Ceramic (MLCC), 1uF, ±10%, 50V, X7R, ±10%, SMD 1206; Manufacturer: TDK; Manufacturer Part Number: C3216X7R1H105KT000N
footprint CAP-1206 (1206 (3216M) Capacitor)
pins: 1, 2

## C3216X7R1H106KT0A0E
designator C?  Capacitance: 10uF  (hidden comment: *)
Capacitor, Ceramic (MLCC), 10uF, ±10%, 50V, X7R, ±10%, SMD 1206; Manufacturer: TDK; Manufacturer Part Number: C3216X7R1H106KT0A0E
footprint CAP-1206 (1206 (3216M) Capacitor)
pins: 1, 2

## C3216X7R1H224KT0J0N
designator C?  Capacitance: 220nF  (hidden comment: *)
Capacitor, Ceramic (MLCC), 220nF, ±10%, 50V, X7R, ±10%, SMD 1206; Manufacturer: TDK; Manufacturer Part Number: C3216X7R1H224KT0J0N
footprint CAP-1206 (1206 (3216M) Capacitor)
pins: 1, 2

## C3216X7R1H224KT0K0N
designator C?  Capacitance: 220nF  (hidden comment: *)
Capacitor, Ceramic (MLCC), 220nF, ±10%, 50V, X7R, ±10%, SMD 1206; Manufacturer: TDK; Manufacturer Part Number: C3216X7R1H224KT0K0N
footprint CAP-1206 (1206 (3216M) Capacitor)
pins: 1, 2

## C3216X7R1H225KT000E
designator C?  Capacitance: 2.2uF  (hidden comment: *)
Capacitor, Ceramic (MLCC), 2.2uF, ±10%, 50V, X7R, ±10%, SMD 1206; Manufacturer: TDK; Manufacturer Part Number: C3216X7R1H225KT000E
footprint CAP-1206 (1206 (3216M) Capacitor)
pins: 1, 2

## C3216X7R1H225KT000S
designator C?  Capacitance: 2.2uF  (hidden comment: *)
Capacitor, Ceramic (MLCC), 2.2uF, ±10%, 50V, X7R, ±10%, SMD 1206; Manufacturer: TDK; Manufacturer Part Number: C3216X7R1H225KT000S
footprint CAP-1206 (1206 (3216M) Capacitor)
pins: 1, 2

## C3216X7R1H474KT000N
designator C?  Capacitance: 470nF  (hidden comment: *)
Capacitor, Ceramic (MLCC), 470nF, ±10%, 50V, X7R, ±10%, SMD 1206; Manufacturer: TDK; Manufacturer Part Number: C3216X7R1H474KT000N
footprint CAP-1206 (1206 (3216M) Capacitor)
pins: 1, 2

## C3216X7R1H475KT000E
designator C?  Capacitance: 4.7uF  (hidden comment: *)
Capacitor, Ceramic (MLCC), 4.7uF, ±10%, 50V, X7R, ±10%, SMD 1206; Manufacturer: TDK; Manufacturer Part Number: C3216X7R1H475KT000E
footprint CAP-1206 (1206 (3216M) Capacitor)
pins: 1, 2

## C3216X7R1H684KT000N
designator C?  Capacitance: 680nF  (hidden comment: *)
Capacitor, Ceramic (MLCC), 680nF, ±10%, 50V, X7R, ±10%, SMD 1206; Manufacturer: TDK; Manufacturer Part Number: C3216X7R1H684KT000N
footprint CAP-1206 (1206 (3216M) Capacitor)
pins: 1, 2

## C3216X7R1V106KT000E
designator C?  Capacitance: 10uF  (hidden comment: *)
Capacitor, Ceramic (MLCC), 10uF, ±10%, 35V, X7R, ±10%, SMD 1206; Manufacturer: TDK; Manufacturer Part Number: C3216X7R1V106KT000E
footprint CAP-1206 (1206 (3216M) Capacitor)
pins: 1, 2

## C3216X7R1V106MT000E
designator C?  Capacitance: 10uF  (hidden comment: *)
Capacitor, Ceramic (MLCC), 10uF, ±20%, 35V, X7R, ±20%, SMD 1206; Manufacturer: TDK; Manufacturer Part Number: C3216X7R1V106MT000E
footprint CAP-1206 (1206 (3216M) Capacitor)
pins: 1, 2

## C3216X7R1V685KT000E
designator C?  Capacitance: 6.8uF  (hidden comment: *)
Capacitor, Ceramic (MLCC), 6.8uF, ±10%, 35V, X7R, ±10%, SMD 1206; Manufacturer: TDK; Manufacturer Part Number: C3216X7R1V685KT000E
footprint CAP-1206 (1206 (3216M) Capacitor)
pins: 1, 2

## C3216X7R2A104KT020U
designator C?  Capacitance: 100nF  (hidden comment: *)
Capacitor, Ceramic (MLCC), 100nF, ±10%, 100V, X7R, ±10%, SMD 1206; Manufacturer: TDK; Manufacturer Part Number: C3216X7R2A104KT020U
footprint CAP-1206 (1206 (3216M) Capacitor)
pins: 1, 2

## C3216X7R2A105KT0L0U
designator C?  Capacitance: 1uF  (hidden comment: *)
Capacitor, Ceramic (MLCC), 1uF, ±10%, 100V, X7R, ±10%, SMD 1206; Manufacturer: TDK; Manufacturer Part Number: C3216X7R2A105KT0L0U
footprint CAP-1206 (1206 (3216M) Capacitor)
pins: 1, 2

## C3216X7R2A105KT5L0U
designator C?  Capacitance: 1uF  (hidden comment: *)
Capacitor, Ceramic (MLCC), 1uF, ±10%, 100V, X7R, ±10%, SMD 1206; Manufacturer: TDK; Manufacturer Part Number: C3216X7R2A105KT5L0U
footprint CAP-1206 (1206 (3216M) Capacitor)
pins: 1, 2

## C3216X7R2A154KT0L0U
designator C?  Capacitance: 150nF  (hidden comment: *)
Capacitor, Ceramic (MLCC), 150nF, ±10%, 100V, X7R, ±10%, SMD 1206; Manufacturer: TDK; Manufacturer Part Number: C3216X7R2A154KT0L0U
footprint CAP-1206 (1206 (3216M) Capacitor)
pins: 1, 2

## C3216X7R2A224KT0L0U
designator C?  Capacitance: 220nF  (hidden comment: *)
Capacitor, Ceramic (MLCC), 220nF, ±10%, 100V, X7R, ±10%, SMD 1206; Manufacturer: TDK; Manufacturer Part Number: C3216X7R2A224KT0L0U
footprint CAP-1206 (1206 (3216M) Capacitor)
pins: 1, 2

## C3216X7R2A334KT0L0U
designator C?  Capacitance: 330nF  (hidden comment: *)
Capacitor, Ceramic (MLCC), 330nF, ±10%, 100V, X7R, ±10%, SMD 1206; Manufacturer: TDK; Manufacturer Part Number: C3216X7R2A334KT0L0U
footprint CAP-1206 (1206 (3216M) Capacitor)
pins: 1, 2

## C3216X7R2A474KT0L0U
designator C?  Capacitance: 470nF  (hidden comment: *)
Capacitor, Ceramic (MLCC), 470nF, ±10%, 100V, X7R, ±10%, SMD 1206; Manufacturer: TDK; Manufacturer Part Number: C3216X7R2A474KT0L0U
footprint CAP-1206 (1206 (3216M) Capacitor)
pins: 1, 2

## C3216X7R2E104KT0L0U
designator C?  Capacitance: 100nF  (hidden comment: *)
Capacitor, Ceramic (MLCC), 100nF, ±10%, 250V, X7R, ±10%, SMD 1206; Manufacturer: TDK; Manufacturer Part Number: C3216X7R2E104KT0L0U
footprint CAP-1206 (1206 (3216M) Capacitor)
pins: 1, 2

## C3216X7R2E223KT020U
designator C?  Capacitance: 22nF  (hidden comment: *)
Capacitor, Ceramic (MLCC), 22nF, ±10%, 250V, X7R, ±10%, SMD 1206; Manufacturer: TDK; Manufacturer Part Number: C3216X7R2E223KT020U
footprint CAP-1206 (1206 (3216M) Capacitor)
pins: 1, 2

## C3216X7R2E473KT020U
designator C?  Capacitance: 47nF  (hidden comment: *)
Capacitor, Ceramic (MLCC), 47nF, ±10%, 250V, X7R, ±10%, SMD 1206; Manufacturer: TDK; Manufacturer Part Number: C3216X7R2E473KT020U
footprint CAP-1206 (1206 (3216M) Capacitor)
pins: 1, 2

## C3216X7R2E683KT0L0U
designator C?  Capacitance: 68nF  (hidden comment: *)
Capacitor, Ceramic (MLCC), 68nF, ±10%, 250V, X7R, ±10%, SMD 1206; Manufacturer: TDK; Manufacturer Part Number: C3216X7R2E683KT0L0U
footprint CAP-1206 (1206 (3216M) Capacitor)
pins: 1, 2

## C3216X7R2J102KT020U
designator C?  Capacitance: 1nF  (hidden comment: *)
Capacitor, Ceramic (MLCC), 1nF, ±10%, 630V, X7R, ±10%, SMD 1206; Manufacturer: TDK; Manufacturer Part Number: C3216X7R2J102KT020U
footprint CAP-1206 (1206 (3216M) Capacitor)
pins: 1, 2

## C3216X7R2J103KT020U
designator C?  Capacitance: 10nF  (hidden comment: *)
Capacitor, Ceramic (MLCC), 10nF, ±10%, 630V, X7R, ±10%, SMD 1206; Manufacturer: TDK; Manufacturer Part Number: C3216X7R2J103KT020U
footprint CAP-1206 (1206 (3216M) Capacitor)
pins: 1, 2

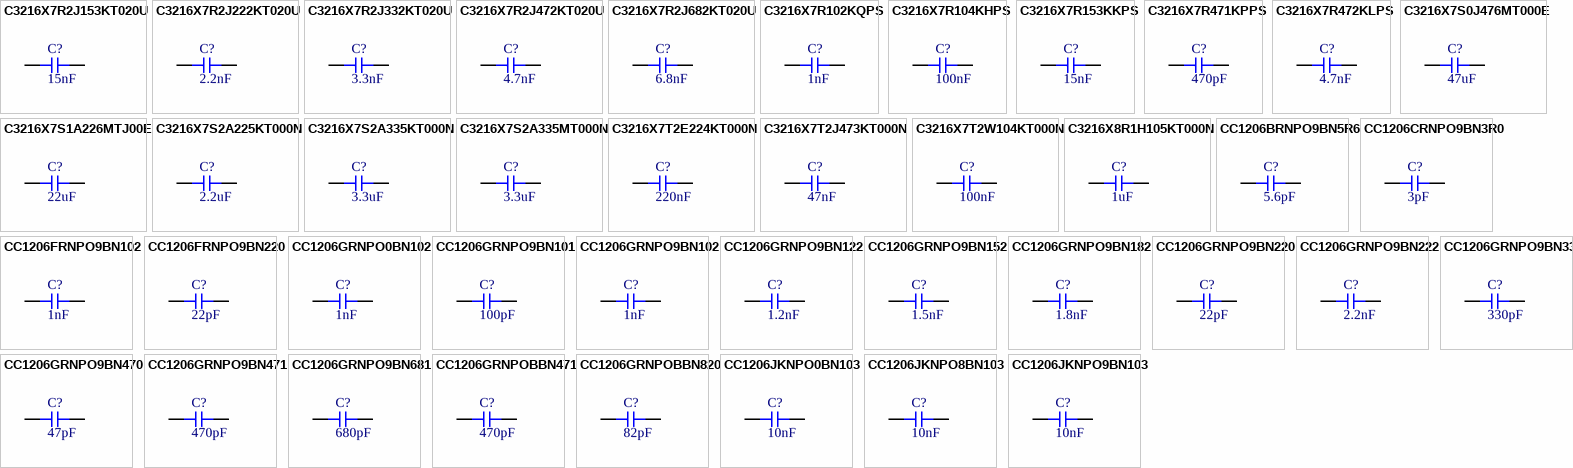
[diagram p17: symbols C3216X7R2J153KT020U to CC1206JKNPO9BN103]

## C3216X7R2J153KT020U
designator C?  Capacitance: 15nF  (hidden comment: *)
Capacitor, Ceramic (MLCC), 15nF, ±10%, 630V, X7R, ±10%, SMD 1206; Manufacturer: TDK; Manufacturer Part Number: C3216X7R2J153KT020U
footprint CAP-1206 (1206 (3216M) Capacitor)
pins: 1, 2

## C3216X7R2J222KT020U
designator C?  Capacitance: 2.2nF  (hidden comment: *)
Capacitor, Ceramic (MLCC), 2.2nF, ±10%, 630V, X7R, ±10%, SMD 1206; Manufacturer: TDK; Manufacturer Part Number: C3216X7R2J222KT020U
footprint CAP-1206 (1206 (3216M) Capacitor)
pins: 1, 2

## C3216X7R2J332KT020U
designator C?  Capacitance: 3.3nF  (hidden comment: *)
Capacitor, Ceramic (MLCC), 3.3nF, ±10%, 630V, X7R, ±10%, SMD 1206; Manufacturer: TDK; Manufacturer Part Number: C3216X7R2J332KT020U
footprint CAP-1206 (1206 (3216M) Capacitor)
pins: 1, 2

## C3216X7R2J472KT020U
designator C?  Capacitance: 4.7nF  (hidden comment: *)
Capacitor, Ceramic (MLCC), 4.7nF, ±10%, 630V, X7R, ±10%, SMD 1206; Manufacturer: TDK; Manufacturer Part Number: C3216X7R2J472KT020U
footprint CAP-1206 (1206 (3216M) Capacitor)
pins: 1, 2

## C3216X7R2J682KT020U
designator C?  Capacitance: 6.8nF  (hidden comment: *)
Capacitor, Ceramic (MLCC), 6.8nF, ±10%, 630V, X7R, ±10%, SMD 1206; Manufacturer: TDK; Manufacturer Part Number: C3216X7R2J682KT020U
footprint CAP-1206 (1206 (3216M) Capacitor)
pins: 1, 2

## C3216X7R102KQPS
designator C?  Capacitance: 1nF  (hidden comment: *)
Capacitor, Ceramic (MLCC), 1nF, ±10%, 2kV, X7R, ±10%, SMD 1206; Manufacturer: Darfon Elec; Manufacturer Part Number: C3216X7R102KQPS
footprint CAP-1206 (1206 (3216M) Capacitor)
pins: 1, 2

## C3216X7R104KHPS
designator C?  Capacitance: 100nF  (hidden comment: *)
Capacitor, Ceramic (MLCC), 100nF, ±10%, 100V, X7R, ±10%, SMD 1206; Manufacturer: Darfon Elec; Manufacturer Part Number: C3216X7R104KHPS
footprint CAP-1206 (1206 (3216M) Capacitor)
pins: 1, 2

## C3216X7R153KKPS
designator C?  Capacitance: 15nF  (hidden comment: *)
Capacitor, Ceramic (MLCC), 15nF, ±10%, 250V, X7R, ±10%, SMD 1206; Manufacturer: Darfon Elec; Manufacturer Part Number: C3216X7R153KKPS
footprint CAP-1206 (1206 (3216M) Capacitor)
pins: 1, 2

## C3216X7R471KPPS
designator C?  Capacitance: 470pF  (hidden comment: *)
Capacitor, Ceramic (MLCC), 470pF, ±10%, 1kV, X7R, ±10%, SMD 1206; Manufacturer: Darfon Elec; Manufacturer Part Number: C3216X7R471KPPS
footprint CAP-1206 (1206 (3216M) Capacitor)
pins: 1, 2

## C3216X7R472KLPS
designator C?  Capacitance: 4.7nF  (hidden comment: *)
Capacitor, Ceramic (MLCC), 4.7nF, ±10%, 500V, X7R, ±10%, SMD 1206; Manufacturer: Darfon Elec; Manufacturer Part Number: C3216X7R472KLPS
footprint CAP-1206 (1206 (3216M) Capacitor)
pins: 1, 2

## C3216X7S0J476MT000E
designator C?  Capacitance: 47uF  (hidden comment: *)
Capacitor, Ceramic (MLCC), 47uF, ±20%, 6.3V, X7S, ±20%, SMD 1206; Manufacturer: TDK; Manufacturer Part Number: C3216X7S0J476MT000E
footprint CAP-1206 (1206 (3216M) Capacitor)
pins: 1, 2

## C3216X7S1A226MTJ00E
designator C?  Capacitance: 22uF  (hidden comment: *)
Capacitor, Ceramic (MLCC), 22uF, ±20%, 10V, X7S, ±20%, SMD 1206; Manufacturer: TDK; Manufacturer Part Number: C3216X7S1A226MTJ00E
footprint CAP-1206 (1206 (3216M) Capacitor)
pins: 1, 2

## C3216X7S2A225KT000N
designator C?  Capacitance: 2.2uF  (hidden comment: *)
Capacitor, Ceramic (MLCC), 2.2uF, ±10%, 100V, X7S, ±10%, SMD 1206; Manufacturer: TDK; Manufacturer Part Number: C3216X7S2A225KT000N
footprint CAP-1206 (1206 (3216M) Capacitor)
pins: 1, 2

## C3216X7S2A335KT000N
designator C?  Capacitance: 3.3uF  (hidden comment: *)
Capacitor, Ceramic (MLCC), 3.3uF, ±10%, 100V, X7S, ±10%, SMD 1206; Manufacturer: TDK; Manufacturer Part Number: C3216X7S2A335KT000N
footprint CAP-1206 (1206 (3216M) Capacitor)
pins: 1, 2

## C3216X7S2A335MT000N
designator C?  Capacitance: 3.3uF  (hidden comment: *)
Capacitor, Ceramic (MLCC), 3.3uF, ±20%, 100V, X7S, ±20%, SMD 1206; Manufacturer: TDK; Manufacturer Part Number: C3216X7S2A335MT000N
footprint CAP-1206 (1206 (3216M) Capacitor)
pins: 1, 2

## C3216X7T2E224KT000N
designator C?  Capacitance: 220nF  (hidden comment: *)
Capacitor, Ceramic (MLCC), 220nF, ±10%, 250V, X7T, ±10%, SMD 1206; Manufacturer: TDK; Manufacturer Part Number: C3216X7T2E224KT000N
footprint CAP-1206 (1206 (3216M) Capacitor)
pins: 1, 2

## C3216X7T2J473KT000N
designator C?  Capacitance: 47nF  (hidden comment: *)
Capacitor, Ceramic (MLCC), 47nF, ±10%, 630V, X7T, ±10%, SMD 1206; Manufacturer: TDK; Manufacturer Part Number: C3216X7T2J473KT000N
footprint CAP-1206 (1206 (3216M) Capacitor)
pins: 1, 2

## C3216X7T2W104KT000N
designator C?  Capacitance: 100nF  (hidden comment: *)
Capacitor, Ceramic (MLCC), 100nF, ±10%, 450V, X7T, ±10%, SMD 1206; Manufacturer: TDK; Manufacturer Part Number: C3216X7T2W104KT000N
footprint CAP-1206 (1206 (3216M) Capacitor)
pins: 1, 2

## C3216X8R1H105KT000N
designator C?  Capacitance: 1uF  (hidden comment: *)
Capacitor, Ceramic (MLCC), 1uF, ±10%, 50V, X8R, ±10%, SMD 1206; Manufacturer: TDK; Manufacturer Part Number: C3216X8R1H105KT000N
footprint CAP-1206 (1206 (3216M) Capacitor)
pins: 1, 2

## CC1206BRNPO9BN5R6
designator C?  Capacitance: 5.6pF  (hidden comment: *)
Capacitor, Ceramic (MLCC), 5.6pF, ±0.1pF, 50V, NP0, ±0.1pF, SMD 1206; Manufacturer: YAGEO; Manufacturer Part Number: CC1206BRNPO9BN5R6
footprint CAP-1206 (1206 (3216M) Capacitor)
pins: 1, 2

## CC1206CRNPO9BN3R0
designator C?  Capacitance: 3pF  (hidden comment: *)
Capacitor, Ceramic (MLCC), 3pF, ±0.25pF, 50V, NP0, ±0.25pF, SMD 1206; Manufacturer: YAGEO; Manufacturer Part Number: CC1206CRNPO9BN3R0
footprint CAP-1206 (1206 (3216M) Capacitor)
pins: 1, 2

## CC1206FRNPO9BN102
designator C?  Capacitance: 1nF  (hidden comment: *)
Capacitor, Ceramic (MLCC), 1nF, ±1pF, 50V, NP0, ±1pF, SMD 1206; Manufacturer: YAGEO; Manufacturer Part Number: CC1206FRNPO9BN102
footprint CAP-1206 (1206 (3216M) Capacitor)
pins: 1, 2

## CC1206FRNPO9BN220
designator C?  Capacitance: 22pF  (hidden comment: *)
Capacitor, Ceramic (MLCC), 22pF, ±1pF, 50V, NP0, ±1pF, SMD 1206; Manufacturer: YAGEO; Manufacturer Part Number: CC1206FRNPO9BN220
footprint CAP-1206 (1206 (3216M) Capacitor)
pins: 1, 2

## CC1206GRNPO0BN102
designator C?  Capacitance: 1nF  (hidden comment: *)
Capacitor, Ceramic (MLCC), 1nF, ±2%, 100V, NP0, ±2%, SMD 1206; Manufacturer: YAGEO; Manufacturer Part Number: CC1206GRNPO0BN102
footprint CAP-1206 (1206 (3216M) Capacitor)
pins: 1, 2

## CC1206GRNPO9BN101
designator C?  Capacitance: 100pF  (hidden comment: *)
Capacitor, Ceramic (MLCC), 100pF, ±2%, 50V, NP0, ±2%, SMD 1206; Manufacturer: YAGEO; Manufacturer Part Number: CC1206GRNPO9BN101
footprint CAP-1206 (1206 (3216M) Capacitor)
pins: 1, 2

## CC1206GRNPO9BN102
designator C?  Capacitance: 1nF  (hidden comment: *)
Capacitor, Ceramic (MLCC), 1nF, ±2%, 50V, NP0, ±2%, SMD 1206; Manufacturer: YAGEO; Manufacturer Part Number: CC1206GRNPO9BN102
footprint CAP-1206 (1206 (3216M) Capacitor)
pins: 1, 2

## CC1206GRNPO9BN122
designator C?  Capacitance: 1.2nF  (hidden comment: *)
Capacitor, Ceramic (MLCC), 1.2nF, ±2%, 50V, NP0, ±2%, SMD 1206; Manufacturer: YAGEO; Manufacturer Part Number: CC1206GRNPO9BN122
footprint CAP-1206 (1206 (3216M) Capacitor)
pins: 1, 2

## CC1206GRNPO9BN152
designator C?  Capacitance: 1.5nF  (hidden comment: *)
Capacitor, Ceramic (MLCC), 1.5nF, ±2%, 50V, NP0, ±2%, SMD 1206; Manufacturer: YAGEO; Manufacturer Part Number: CC1206GRNPO9BN152
footprint CAP-1206 (1206 (3216M) Capacitor)
pins: 1, 2

## CC1206GRNPO9BN182
designator C?  Capacitance: 1.8nF  (hidden comment: *)
Capacitor, Ceramic (MLCC), 1.8nF, ±2%, 50V, NP0, ±2%, SMD 1206; Manufacturer: YAGEO; Manufacturer Part Number: CC1206GRNPO9BN182
footprint CAP-1206 (1206 (3216M) Capacitor)
pins: 1, 2

## CC1206GRNPO9BN220
designator C?  Capacitance: 22pF  (hidden comment: *)
Capacitor, Ceramic (MLCC), 22pF, ±2%, 50V, NP0, ±2%, SMD 1206; Manufacturer: YAGEO; Manufacturer Part Number: CC1206GRNPO9BN220
footprint CAP-1206 (1206 (3216M) Capacitor)
pins: 1, 2

## CC1206GRNPO9BN222
designator C?  Capacitance: 2.2nF  (hidden comment: *)
Capacitor, Ceramic (MLCC), 2.2nF, ±2%, 50V, NP0, ±2%, SMD 1206; Manufacturer: YAGEO; Manufacturer Part Number: CC1206GRNPO9BN222
footprint CAP-1206 (1206 (3216M) Capacitor)
pins: 1, 2

## CC1206GRNPO9BN331
designator C?  Capacitance: 330pF  (hidden comment: *)
Capacitor, Ceramic (MLCC), 330pF, ±2%, 50V, NP0, ±2%, SMD 1206; Manufacturer: YAGEO; Manufacturer Part Number: CC1206GRNPO9BN331
footprint CAP-1206 (1206 (3216M) Capacitor)
pins: 1, 2

## CC1206GRNPO9BN470
designator C?  Capacitance: 47pF  (hidden comment: *)
Capacitor, Ceramic (MLCC), 47pF, ±2%, 50V, NP0, ±2%, SMD 1206; Manufacturer: YAGEO; Manufacturer Part Number: CC1206GRNPO9BN470
footprint CAP-1206 (1206 (3216M) Capacitor)
pins: 1, 2

## CC1206GRNPO9BN471
designator C?  Capacitance: 470pF  (hidden comment: *)
Capacitor, Ceramic (MLCC), 470pF, ±2%, 50V, NP0, ±2%, SMD 1206; Manufacturer: YAGEO; Manufacturer Part Number: CC1206GRNPO9BN471
footprint CAP-1206 (1206 (3216M) Capacitor)
pins: 1, 2

## CC1206GRNPO9BN681
designator C?  Capacitance: 680pF  (hidden comment: *)
Capacitor, Ceramic (MLCC), 680pF, ±2%, 50V, NP0, ±2%, SMD 1206; Manufacturer: YAGEO; Manufacturer Part Number: CC1206GRNPO9BN681
footprint CAP-1206 (1206 (3216M) Capacitor)
pins: 1, 2

## CC1206GRNPOBBN471
designator C?  Capacitance: 470pF  (hidden comment: *)
Capacitor, Ceramic (MLCC), 470pF, ±2%, 500V, NP0, ±2%, SMD 1206; Manufacturer: YAGEO; Manufacturer Part Number: CC1206GRNPOBBN471
footprint CAP-1206 (1206 (3216M) Capacitor)
pins: 1, 2

## CC1206GRNPOBBN820
designator C?  Capacitance: 82pF  (hidden comment: *)
Capacitor, Ceramic (MLCC), 82pF, ±2%, 500V, NP0, ±2%, SMD 1206; Manufacturer: YAGEO; Manufacturer Part Number: CC1206GRNPOBBN820
footprint CAP-1206 (1206 (3216M) Capacitor)
pins: 1, 2

## CC1206JKNPO0BN103
designator C?  Capacitance: 10nF  (hidden comment: *)
Capacitor, Ceramic (MLCC), 10nF, ±5%, 100V, NP0, ±5%, SMD 1206; Manufacturer: YAGEO; Manufacturer Part Number: CC1206JKNPO0BN103
footprint CAP-1206 (1206 (3216M) Capacitor)
pins: 1, 2

## CC1206JKNPO8BN103
designator C?  Capacitance: 10nF  (hidden comment: *)
Capacitor, Ceramic (MLCC), 10nF, ±5%, 25V, NP0, ±5%, SMD 1206; Manufacturer: YAGEO; Manufacturer Part Number: CC1206JKNPO8BN103
footprint CAP-1206 (1206 (3216M) Capacitor)
pins: 1, 2

## CC1206JKNPO9BN103
designator C?  Capacitance: 10nF  (hidden comment: *)
Capacitor, Ceramic (MLCC), 10nF, ±5%, 50V, NP0, ±5%, SMD 1206; Manufacturer: YAGEO; Manufacturer Part Number: CC1206JKNPO9BN103
footprint CAP-1206 (1206 (3216M) Capacitor)
pins: 1, 2

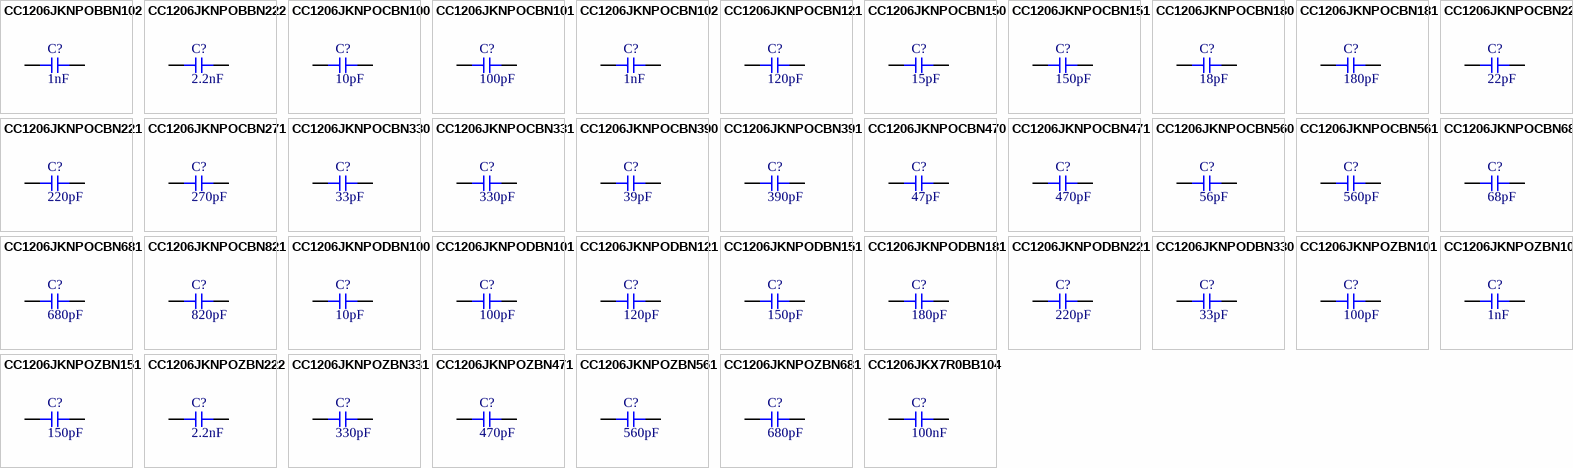
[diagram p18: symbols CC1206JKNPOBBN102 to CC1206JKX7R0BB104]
